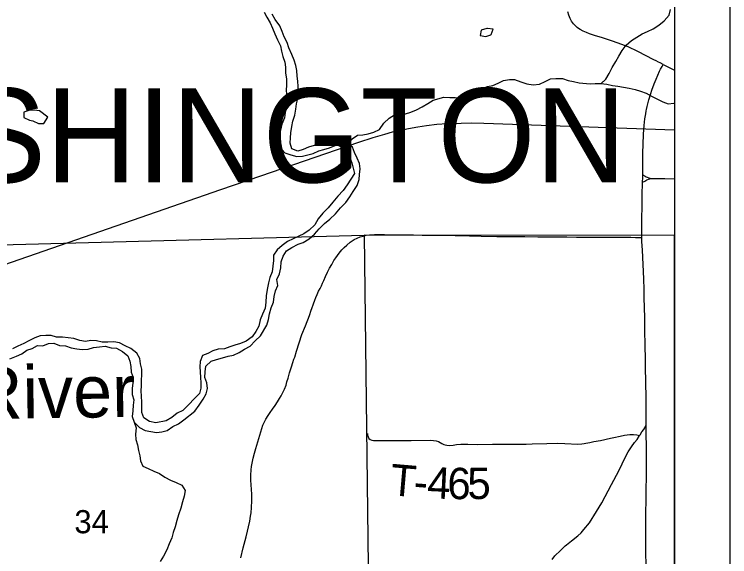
# Model space of a CAD drawing. Extents: x 0 to 34, y 0 to 22.
# Drawn here: x 7.465 to 8.76, y 17.19 to 18.172 of the extents above; entities that cross this region are included whole.
import ezdxf

# ---------------------------------------------------------------- set-up
doc = ezdxf.new("R2010")
doc.units = 0
for name, color, linetype in [('GM_X_County_Road', 7, 'Continuous'), ('GM_X_County_Road_Text', 7, 'Continuous'), ('GM_X_County_Text', 7, 'Continuous'), ('GM_X_Interchange_Ramps', 7, 'Continuous'), ('GM_X_Major_River', 7, 'Continuous'), ('GM_X_Minor_River_Text', 7, 'Continuous'), ('GM_X_State_Location', 7, 'Continuous'), ('GM_X_State_Route', 7, 'Continuous'), ('GM_X_State_Shield', 7, 'Continuous'), ('GM_X_Township_Road', 7, 'Continuous'), ('GM_X_Township_Text', 7, 'Continuous'), ('GM_X_Unincorporated_Location', 7, 'Continuous'), ('SH_Data', 7, 'Continuous')]:
    doc.layers.add(name, color=color, linetype=linetype)

msp = doc.modelspace()

# ---------------------------------------------------------------- linework, layer by layer
at = {"layer": 'GM_X_County_Road'}
for points in [[(8.6401, 18.0811), (8.6346, 18.084), (8.6315, 18.0856), (8.6274, 18.0876), (8.6231, 18.0897), (8.5941, 18.1046), (8.5767, 18.1129), (8.5653, 18.1176), (8.5484, 18.1234), (8.5301, 18.1292), (8.5154, 18.1338), (8.5067, 18.1366), (8.5011, 18.1388), (8.495, 18.1414), (8.4893, 18.1444), (8.4865, 18.1462), (8.4844, 18.1479), (8.4821, 18.1499), (8.4797, 18.1521), (8.4776, 18.1545), (8.4756, 18.157), (8.474, 18.1596), (8.4714, 18.1643), (8.469, 18.1705), (8.4671, 18.1765)], [(8.6088, 17.1756), (8.6085, 17.1973), (8.6082, 17.2377), (8.6083, 17.2594), (8.6093, 17.3029), (8.6096, 17.3437), (8.6098, 17.3742), (8.6093, 17.4274), (8.609, 17.4542), (8.6088, 17.4795), (8.6087, 17.5043), (8.6079, 17.5353), (8.6077, 17.5477), (8.6072, 17.5726), (8.6067, 17.6005), (8.6064, 17.6223), (8.6057, 17.6595), (8.6054, 17.6738), (8.6049, 17.6934), (8.6023, 17.7452), (8.6013, 17.7607), (8.6012, 17.7682), (8.601, 17.7822), (8.602, 17.844), (8.6027, 17.8679), (8.603, 17.8764), (8.603, 17.8815), (8.6032, 17.8918), (8.603, 17.9054), (8.6031, 17.921), (8.6034, 17.9366), (8.6045, 17.955), (8.6055, 17.9707), (8.6069, 17.9829), (8.6082, 17.9918), (8.6091, 17.9974), (8.6096, 17.9998), (8.6108, 18.005), (8.6138, 18.0169), (8.6173, 18.0287), (8.6193, 18.0345), (8.6235, 18.0462), (8.627, 18.0548), (8.6333, 18.0689), (8.6351, 18.0725), (8.6379, 18.0775), (8.6401, 18.0811)], [(8.6401, 18.0811), (8.6593, 18.0716), (8.6602, 18.0712)]]:
    msp.add_lwpolyline(points, dxfattribs=at)
at = {"layer": 'GM_X_County_Road_Text'}
for points in [[(8.5275, 18.0465), (8.5362, 18.0545), (8.542, 18.0646), (8.5478, 18.0756), (8.5543, 18.0865), (8.5593, 18.0963), (8.5655, 18.1065), (8.5728, 18.1163), (8.5827, 18.1246), (8.5922, 18.1309), (8.6021, 18.1369), (8.6116, 18.141), (8.6215, 18.1458), (8.6322, 18.1522), (8.6417, 18.1604), (8.6505, 18.1706), (8.6533, 18.1808)], [(8.0676, 17.9389), (8.0771, 17.9467), (8.0866, 17.9531), (8.0961, 17.9541), (8.1056, 17.9556), (8.1162, 17.9585), (8.1265, 17.9637), (8.1342, 17.975), (8.1437, 17.9837), (8.1533, 17.99), (8.1627, 17.9903), (8.1734, 17.9921), (8.1833, 17.9951), (8.1935, 17.9992), (8.2038, 18.0047), (8.2141, 18.0103), (8.2236, 18.0167), (8.2426, 18.0218), (8.2536, 18.0214), (8.2634, 18.0213), (8.2733, 18.0208), (8.2835, 18.0207), (8.293, 18.0248), (8.303, 18.0323), (8.3125, 18.0379), (8.322, 18.0412), (8.3315, 18.043), (8.3414, 18.0475), (8.3509, 18.0523), (8.3615, 18.0541), (8.371, 18.0541), (8.3823, 18.0498), (8.3933, 18.0459), (8.4046, 18.0446), (8.416, 18.0457), (8.4263, 18.0501), (8.4358, 18.055), (8.4453, 18.056), (8.4574, 18.0555), (8.4676, 18.0524), (8.4775, 18.0501), (8.4877, 18.0477), (8.5074, 18.046), (8.5168, 18.0467), (8.5271, 18.0466), (8.5377, 18.0453), (8.5479, 18.043), (8.5577, 18.0421), (8.5782, 18.0381), (8.5892, 18.0358), (8.599, 18.033), (8.6088, 18.0295), (8.6186, 18.0237), (8.6284, 18.0187), (8.639, 18.0137), (8.6488, 18.0098), (8.6591, 18.0112), (8.6602, 18.0113)], [(8.5315, 18.0502), (8.5323, 18.0509)], [(7.6824, 17.4338), (7.6858, 17.4232), (7.6845, 17.4122), (7.6856, 17.4023), (7.6882, 17.3924), (7.69, 17.3825), (7.6926, 17.373), (7.6936, 17.3635), (7.6977, 17.354), (7.7079, 17.3498), (7.7177, 17.3447), (7.7283, 17.3405), (7.7381, 17.3343), (7.7483, 17.3289), (7.7585, 17.3247), (7.7687, 17.3196), (7.7747, 17.3097), (7.7731, 17.2995), (7.7699, 17.2893), (7.7668, 17.2779), (7.7626, 17.2662), (7.7594, 17.2556), (7.7563, 17.2443), (7.7532, 17.2341), (7.7505, 17.2242), (7.7458, 17.2133), (7.7416, 17.2027), (7.7354, 17.1914), (7.7293, 17.1816)]]:
    msp.add_lwpolyline(points, dxfattribs=at)
at = {"layer": 'GM_X_County_Text'}
msp.add_lwpolyline([(7.373, 17.6931), (7.8394, 17.8546), (7.9113, 17.8796), (8.0889, 17.9406), (8.1149, 17.9491), (8.136, 17.9553), (8.15, 17.959), (8.1647, 17.9625), (8.1786, 17.9655), (8.1959, 17.9685), (8.2114, 17.9707), (8.23, 17.973), (8.2488, 17.9744), (8.2739, 17.9752), (8.2934, 17.9753), (8.3154, 17.975), (8.6602, 17.963)], dxfattribs=at)
at = {"layer": 'GM_X_Interchange_Ramps'}
for points in [[(7.8754, 17.188), (7.8799, 17.2061), (7.8848, 17.2264), (7.8914, 17.2544), (7.8931, 17.2636), (7.8939, 17.2697), (7.8947, 17.279), (7.8955, 17.2915), (7.8955, 17.3031), (7.8934, 17.3287), (7.8933, 17.338), (7.8938, 17.3473), (7.8946, 17.3535), (7.8956, 17.3596), (7.8976, 17.3685), (7.9001, 17.3774), (7.9026, 17.3863), (7.9063, 17.3981), (7.9098, 17.4104), (7.9155, 17.4283), (7.9209, 17.4391), (7.925, 17.4457), (7.9286, 17.4511), (7.9329, 17.4572), (7.9373, 17.4636), (7.9416, 17.4703), (7.9454, 17.4767), (7.9481, 17.4816), (7.9516, 17.4876), (7.9544, 17.4933), (7.9572, 17.5007), (7.9589, 17.5066), (7.9608, 17.5132), (7.9636, 17.5228), (7.9669, 17.5337), (7.9695, 17.5414), (7.9715, 17.5475), (7.9729, 17.5516), (7.9764, 17.5621), (7.9811, 17.5775), (7.9857, 17.5923), (7.9922, 17.608), (7.9996, 17.6269), (8.0029, 17.6363), (8.0039, 17.6393), (8.0069, 17.6478), (8.0094, 17.6545), (8.0113, 17.6595), (8.0137, 17.6645), (8.0162, 17.6707), (8.0188, 17.6759), (8.0211, 17.6807), (8.0233, 17.6852), (8.0254, 17.69), (8.0285, 17.6974), (8.0323, 17.7055), (8.036, 17.7124), (8.0399, 17.7192), (8.044, 17.7265), (8.0474, 17.7314), (8.0502, 17.7355), (8.0535, 17.7399), (8.0583, 17.7454), (8.0624, 17.7497), (8.067, 17.7541), (8.0733, 17.7593), (8.0806, 17.7643), (8.0857, 17.7668), (8.0911, 17.7689), (8.0967, 17.7706), (8.1024, 17.7719), (8.1083, 17.7727), (8.1172, 17.7733), (8.1258, 17.7733), (8.1322, 17.7733), (8.1353, 17.7732), (8.1414, 17.7729), (8.1587, 17.7728), (8.1734, 17.7727), (8.188, 17.7725), (8.2035, 17.7724), (8.2196, 17.7723), (8.2372, 17.7721), (8.2539, 17.772), (8.2632, 17.7718), (8.272, 17.7716), (8.2893, 17.7711), (8.3102, 17.7706), (8.339, 17.7699), (8.3566, 17.7698), (8.371, 17.7697), (8.3896, 17.7695), (8.4128, 17.7694), (8.4401, 17.7691), (8.4657, 17.7689), (8.4827, 17.7688), (8.4921, 17.7688), (8.5018, 17.7687), (8.5156, 17.7686), (8.5279, 17.7686), (8.5407, 17.7685), (8.5524, 17.7684), (8.5636, 17.7684), (8.5735, 17.7683), (8.5813, 17.7683), (8.5896, 17.7682), (8.5962, 17.7682), (8.6012, 17.7682)], [(8.597, 17.4093), (8.5982, 17.411), (8.6015, 17.4159), (8.6047, 17.4206), (8.6093, 17.4274)], [(8.1047, 17.4132), (8.1049, 17.4101), (8.1056, 17.4071), (8.107, 17.4044), (8.1094, 17.4024), (8.1122, 17.4012), (8.1153, 17.4006), (8.1184, 17.4004), (8.1433, 17.4003), (8.1837, 17.4004), (8.2179, 17.401), (8.2243, 17.4006), (8.2288, 17.3998), (8.233, 17.3984), (8.239, 17.3952), (8.2431, 17.3934), (8.2453, 17.3928), (8.248, 17.392), (8.2526, 17.3916), (8.2597, 17.392), (8.2658, 17.3934), (8.2733, 17.3939), (8.2865, 17.394), (8.3037, 17.3934), (8.3309, 17.3937), (8.3589, 17.3938), (8.3775, 17.3939), (8.3919, 17.394), (8.4029, 17.3943), (8.4295, 17.395), (8.4488, 17.3955), (8.4621, 17.3953), (8.4856, 17.3941), (8.4928, 17.3945), (8.4966, 17.395), (8.4999, 17.3954), (8.5073, 17.3969), (8.5146, 17.3984), (8.5266, 17.4007), (8.5443, 17.4046), (8.5503, 17.4059), (8.5619, 17.4084), (8.5701, 17.4102), (8.5797, 17.4116), (8.5864, 17.4116), (8.5922, 17.4106), (8.597, 17.4093)], [(8.4387, 17.1853), (8.444, 17.1918), (8.4537, 17.2011), (8.4602, 17.2077), (8.4626, 17.2097), (8.465, 17.2115), (8.4738, 17.219), (8.4851, 17.2279), (8.4915, 17.2336), (8.4965, 17.2391), (8.5064, 17.2513), (8.5193, 17.2718), (8.529, 17.2879), (8.5465, 17.3208), (8.5594, 17.3456), (8.5716, 17.3709), (8.5766, 17.3801), (8.5823, 17.389), (8.588, 17.3966), (8.5926, 17.4026), (8.597, 17.4093)]]:
    msp.add_lwpolyline(points, dxfattribs=at)
at = {"layer": 'GM_X_Minor_River_Text'}
for points in [[(8.3206, 18.1463), (8.3107, 18.1433), (8.3087, 18.1335), (8.3186, 18.1319), (8.3281, 18.1348), (8.3288, 18.1352)], [(8.3288, 18.1352), (8.3319, 18.145), (8.3217, 18.1463), (8.3206, 18.1463)], [(7.5112, 17.997), (7.5014, 17.9986), (7.4919, 17.9979), (7.4824, 17.995), (7.4827, 17.9851), (7.4929, 17.9801), (7.499, 17.9793)], [(7.499, 17.9793), (7.5092, 17.9746), (7.5186, 17.9745), (7.5259, 17.9855), (7.5112, 17.997)]]:
    msp.add_lwpolyline(points, dxfattribs=at)
at = {"layer": 'GM_X_State_Route'}
msp.add_lwpolyline([(7.1161, 16.8504), (7.0999, 17.7456), (8.0984, 17.7721), (8.1109, 16.7736), (7.5483, 16.7695)], dxfattribs=at)
msp.add_lwpolyline([(8.6602, 16.7776), (8.6602, 17.7718), (8.0984, 17.7721), (8.1109, 16.7736)], close=True, dxfattribs=at)
at = {"layer": 'GM_X_State_Shield'}
for points in [[(7.9179, 18.1761), (7.9224, 18.1666), (7.9284, 18.1567), (7.9328, 18.1471), (7.9369, 18.1365), (7.9418, 18.1258), (7.9474, 18.1148), (7.9492, 18.1053), (7.9517, 18.0954), (7.9551, 18.0855), (7.9561, 18.076), (7.956, 18.0658), (7.9582, 18.0548), (7.9581, 18.0449), (7.9573, 18.0335), (7.9587, 18.024), (7.9567, 18.0138), (7.9574, 18.0043), (7.9554, 17.9945), (7.9542, 17.9846), (7.9496, 17.9733), (7.9472, 17.9623), (7.9441, 17.951), (7.9444, 17.9415), (7.9455, 17.932), (7.9552, 17.9213), (7.9658, 17.9174), (7.9768, 17.9143), (7.987, 17.9153), (7.9965, 17.9175), (8.0064, 17.9201), (8.0163, 17.9249), (8.0258, 17.9271), (8.036, 17.93), (8.049, 17.936), (8.0588, 17.9314), (8.0693, 17.9225), (8.0727, 17.913), (8.0764, 17.9031), (8.0789, 17.8936), (8.0811, 17.8837), (8.0742, 17.8736), (8.0681, 17.863), (8.0604, 17.8528), (8.0508, 17.8427), (8.0417, 17.8318), (8.0336, 17.8216), (8.0241, 17.8118), (8.0156, 17.8017), (8.0095, 17.7911), (7.9988, 17.781), (7.9893, 17.7746), (7.9702, 17.7657), (7.96, 17.7605), (7.9504, 17.7533), (7.9409, 17.7455), (7.9347, 17.7357), (7.9343, 17.7262), (7.9334, 17.7159), (7.9318, 17.7061), (7.9276, 17.6955), (7.9256, 17.6857), (7.9232, 17.6739), (7.9212, 17.6622), (7.9208, 17.6508), (7.9192, 17.6402), (7.9149, 17.6293), (7.9106, 17.6187), (7.9079, 17.6077), (7.9025, 17.5979), (7.8956, 17.5881), (7.8853, 17.5802), (7.875, 17.5762), (7.8648, 17.5732), (7.8553, 17.5699), (7.8458, 17.5662), (7.8344, 17.5659), (7.8249, 17.563), (7.8154, 17.5577), (7.8059, 17.5544), (7.802, 17.5438), (7.8012, 17.534), (7.8018, 17.5245), (7.8021, 17.5146), (7.8028, 17.5051), (7.8031, 17.4953), (7.8004, 17.4854), (7.7912, 17.4757), (7.7813, 17.4655), (7.7706, 17.455), (7.7603, 17.4502), (7.7507, 17.4419), (7.7405, 17.4359), (7.7215, 17.4323), (7.7101, 17.4347), (7.6999, 17.4416), (7.6959, 17.4511), (7.6959, 17.4606), (7.6964, 17.4701), (7.6957, 17.4807), (7.695, 17.4902)], [(8.0911, 17.892), (8.0904, 17.9019), (8.0859, 17.9114), (8.0814, 17.9217), (8.0777, 17.9312), (8.0676, 17.9389), (8.0577, 17.9427), (8.0479, 17.9459), (8.038, 17.9448), (8.0286, 17.943), (8.0179, 17.9385), (8.008, 17.9348), (7.9981, 17.9315), (7.9882, 17.9271), (7.9787, 17.9245), (7.9678, 17.9284), (7.9645, 17.9387), (7.9653, 17.9481), (7.9658, 17.9576), (7.9677, 17.9686), (7.9693, 17.9784), (7.9732, 17.9894), (7.9748, 18), (7.9764, 18.0098), (7.9788, 18.0197), (7.9792, 18.0295), (7.9793, 18.0413), (7.9787, 18.0508), (7.9772, 18.0603), (7.9769, 18.0701), (7.9747, 18.0796), (7.9722, 18.0891), (7.9677, 18.0994), (7.9621, 18.1112), (7.9592, 18.1211), (7.9539, 18.131), (7.9502, 18.1409), (7.9458, 18.1512), (7.9375, 18.1626), (7.9323, 18.1722)], [(7.4571, 17.5485), (7.4693, 17.5529), (7.4788, 17.5574), (7.4883, 17.5641), (7.4978, 17.5671), (7.5073, 17.5723), (7.5172, 17.5718), (7.5271, 17.5759), (7.5366, 17.5766), (7.5471, 17.5723), (7.5578, 17.5718), (7.568, 17.5683), (7.5786, 17.5663), (7.5884, 17.5655), (7.599, 17.5658), (7.6089, 17.5691), (7.6195, 17.5701), (7.6298, 17.5712), (7.6407, 17.5684), (7.6506, 17.5676), (7.6611, 17.5614), (7.6709, 17.5537), (7.6746, 17.5442), (7.6761, 17.5344), (7.6768, 17.5241), (7.6805, 17.5146), (7.6796, 17.5051), (7.6788, 17.4945), (7.6787, 17.4835), (7.6816, 17.474), (7.6808, 17.4642), (7.6796, 17.4543), (7.6787, 17.4437), (7.6824, 17.4338), (7.6918, 17.4239), (7.702, 17.4188), (7.7126, 17.4168), (7.7225, 17.4152), (7.7323, 17.4163), (7.7418, 17.4189), (7.7525, 17.426), (7.7624, 17.4308), (7.7723, 17.4379), (7.7922, 17.4537), (7.8002, 17.4642), (7.8075, 17.4751), (7.8129, 17.485), (7.8152, 17.4948), (7.8138, 17.505), (7.8101, 17.5146), (7.8106, 17.5248), (7.8122, 17.535), (7.8217, 17.5444), (7.8312, 17.5474), (7.8422, 17.5503), (7.8525, 17.5529), (7.8624, 17.555), (7.8722, 17.5595), (7.8818, 17.5659), (7.8921, 17.5715), (7.9016, 17.5809), (7.9112, 17.5899), (7.9227, 17.6095), (7.9254, 17.6197), (7.927, 17.6295), (7.9305, 17.6405), (7.9344, 17.6511), (7.936, 17.6609), (7.9384, 17.6712), (7.9422, 17.681), (7.9408, 17.692), (7.9454, 17.7022), (7.9478, 17.7132), (7.9483, 17.7238), (7.9522, 17.734), (7.9583, 17.7438), (7.9678, 17.7501), (7.9789, 17.7561), (7.9884, 17.7591), (7.999, 17.7654), (8.009, 17.7737), (8.0174, 17.7835), (8.0269, 17.7932), (8.0365, 17.8011), (8.0468, 17.8109), (8.056, 17.8214), (8.0652, 17.8312), (8.0724, 17.8414), (8.0786, 17.8512), (8.0859, 17.8621), (8.0898, 17.8727), (8.0902, 17.8821), (8.0911, 17.892)], [(7.695, 17.4902), (7.6955, 17.4997), (7.6956, 17.5091), (7.6964, 17.5198), (7.6961, 17.5296), (7.6939, 17.5391), (7.6925, 17.549), (7.6873, 17.5585), (7.6764, 17.5673), (7.6658, 17.5716), (7.656, 17.577), (7.6457, 17.579), (7.6348, 17.5787), (7.6241, 17.5784), (7.6139, 17.5808), (7.6037, 17.5813), (7.5942, 17.5795), (7.584, 17.5815), (7.573, 17.585), (7.5526, 17.5874), (7.5416, 17.5875), (7.5318, 17.5906), (7.5223, 17.5903), (7.5124, 17.5897), (7.5025, 17.5864), (7.4919, 17.5808)], [(7.4919, 17.5808), (7.4824, 17.5763), (7.4717, 17.5715), (7.4622, 17.5666)]]:
    msp.add_lwpolyline(points, dxfattribs=at)
at = {"layer": 'GM_X_Township_Road'}
for points in [[(8.6027, 17.8679), (8.6067, 17.8701), (8.6105, 17.8721), (8.6135, 17.8734), (8.6159, 17.8741), (8.6182, 17.8747)], [(8.603, 17.8815), (8.6071, 17.8791), (8.609, 17.878), (8.6111, 17.877), (8.6137, 17.876), (8.6154, 17.8755), (8.6182, 17.8747)], [(8.6182, 17.8747), (8.6282, 17.8749), (8.6427, 17.8746), (8.6602, 17.8739)]]:
    msp.add_lwpolyline(points, dxfattribs=at)
at = {"layer": 'SH_Data'}
for points in [[(1.7602, 21.2866), (8.7602, 21.2866), (8.7602, 14.2866), (1.7602, 14.2866)], [(1.8602, 21.1866), (8.6602, 21.1866), (8.6602, 14.3866), (1.8602, 14.3866)]]:
    msp.add_lwpolyline(points, close=True, dxfattribs=at)

# ---------------------------------------------------------------- texts
at = {"layer": 'GM_X_Major_River'}
msp.add_text('WASHINGTON', height=0.17045, rotation=0, dxfattribs=at).set_placement((7.0032, 17.8677))
at = {"layer": 'GM_X_State_Location'}
msp.add_text('34', height=0.04186, rotation=0, dxfattribs=at).set_placement((7.5741, 17.2326))
at = {"layer": 'GM_X_Township_Text'}
for s, rotation, p in [('T', 355.0997, (8.1439, 17.3018)), ('4', 357.2763, (8.2118, 17.2963)), ('6', 359.2132, (8.2489, 17.2946)), ('5', 1.0514, (8.2859, 17.2941)), ('-', 355.7054, (8.1869, 17.2981))]:
    msp.add_text(s, height=0.0568, rotation=rotation, dxfattribs=at).set_placement(p)
at = {"layer": 'GM_X_Unincorporated_Location'}
msp.add_text('River', height=0.09471, rotation=0.8813, dxfattribs=at).set_placement((7.3896, 17.4388))

doc.saveas('drawing.dxf')
